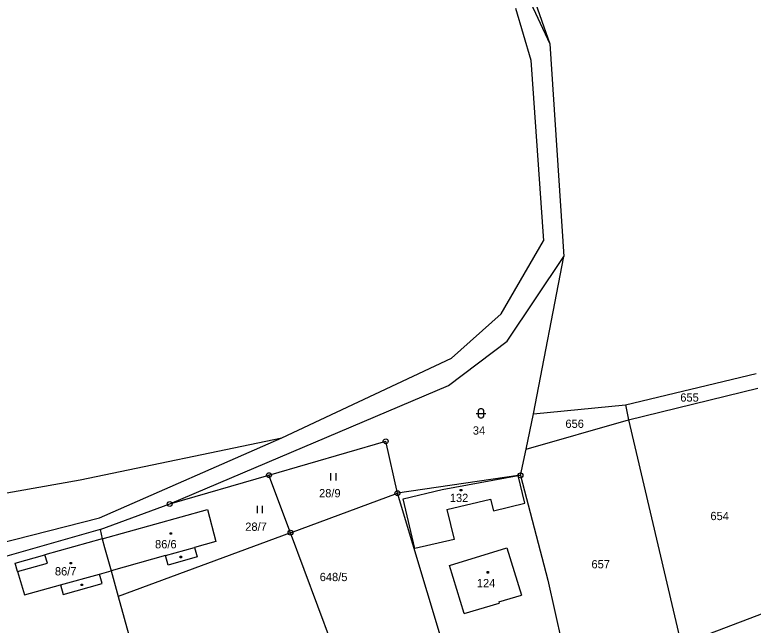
# Model space of a CAD drawing. Extents: x -794142 to -791199, y -1109267 to -1105626.
# Drawn here: x -793464.4 to -793312.7, y -1107558.1 to -1107432.6 of the extents above; entities that cross this region are included whole.
import ezdxf

# ---------------------------------------------------------------- set-up
doc = ezdxf.new("R2010")
doc.units = 0
for name, color, linetype in [('Vrstva 1', 7, 'Continuous'), ('Vrstva 14', 7, 'Continuous'), ('Vrstva 15', 7, 'Continuous'), ('Vrstva 2', 7, 'Continuous'), ('Vrstva 23', 7, 'Continuous'), ('Vrstva 25', 7, 'Continuous'), ('Vrstva 28', 7, 'Continuous')]:
    doc.layers.add(name, color=color, linetype=linetype)

msp = doc.modelspace()

# ---------------------------------------------------------------- linework, layer by layer
at = {"layer": 'Vrstva 1'}
for p, q in [((-793371.44, -1107390.18), (-793354.46, -1107438.54)), ((-793375.72, -1107392.87), (-793354.46, -1107438.54)), ((-793361.55, -1107431.24), (-793358.36, -1107441.93)), ((-793354.46, -1107438.54), (-793351.62, -1107482.26)), ((-793358.36, -1107441.93), (-793355.78, -1107479.02)), ((-793364.52, -1107494.08), (-793355.78, -1107479.02)), ((-793363.27, -1107499.66), (-793351.62, -1107482.26)), ((-793357.81, -1107514.64), (-793351.62, -1107482.26)), ((-793374.67, -1107503.15), (-793364.52, -1107494.08)), ((-793375.33, -1107508.81), (-793363.27, -1107499.66)), ((-793409.53, -1107519.55), (-793374.67, -1107503.15)), ((-793338.94, -1107512.75), (-793312.08, -1107506.35)), ((-793432.59, -1107533.14), (-793375.33, -1107508.81)), ((-793338.31, -1107515.86), (-793311.77, -1107509.33)), ((-793357.81, -1107514.64), (-793338.94, -1107512.75)), ((-793338.94, -1107512.75), (-793338.31, -1107515.86)), ((-793359.37, -1107521.88), (-793357.81, -1107514.64)), ((-793359.37, -1107521.88), (-793338.31, -1107515.86)), ((-793338.31, -1107515.86), (-793327.5, -1107562.01)), ((-793451, -1107528.21), (-793409.53, -1107519.55)), ((-793446.99, -1107536), (-793409.53, -1107519.55)), ((-793412.19, -1107527.22), (-793388.2, -1107520.25)), ((-793385.8, -1107530.91), (-793388.2, -1107520.25)), ((-793360.52, -1107527.26), (-793359.37, -1107521.88)), ((-793432.59, -1107533.14), (-793412.19, -1107527.22)), ((-793407.78, -1107539.04), (-793412.19, -1107527.22)), ((-793360.99, -1107527.28), (-793385.8, -1107530.91)), ((-793376.62, -1107530.18), (-793360.99, -1107527.28)), ((-793360.52, -1107527.26), (-793360.99, -1107527.28)), ((-793359.62, -1107532.97), (-793360.99, -1107527.28)), ((-793360.52, -1107527.26), (-793354.93, -1107548.78)), ((-793504.55, -1107537.5), (-793451, -1107528.21)), ((-793384.61, -1107532.1), (-793376.62, -1107530.18)), ((-793407.78, -1107539.04), (-793385.8, -1107530.91)), ((-793376.27, -1107562.47), (-793385.8, -1107530.91)), ((-793446.9, -1107538.36), (-793432.59, -1107533.14)), ((-793382.2, -1107542.31), (-793384.61, -1107532.1)), ((-793375.67, -1107534.27), (-793366.66, -1107532.13)), ((-793366.66, -1107532.13), (-793366.05, -1107534.58)), ((-793366.05, -1107534.58), (-793359.62, -1107532.97)), ((-793446.44, -1107540.32), (-793424.83, -1107534.3)), ((-793424.83, -1107534.3), (-793423.09, -1107540.85)), ((-793375.67, -1107534.27), (-793374.16, -1107540.45)), ((-793490.03, -1107546.86), (-793446.99, -1107536)), ((-793446.9, -1107538.36), (-793483.13, -1107548.72)), ((-793446.9, -1107538.36), (-793446.44, -1107540.32)), ((-793407.78, -1107539.04), (-793443.16, -1107552.13)), ((-793395.22, -1107572.72), (-793407.78, -1107539.04)), ((-793446.44, -1107540.32), (-793458.22, -1107543.57)), ((-793446.44, -1107540.32), (-793445.96, -1107542.06)), ((-793423.09, -1107540.85), (-793427.47, -1107542.08)), ((-793374.16, -1107540.45), (-793382.2, -1107542.31)), ((-793445.96, -1107542.06), (-793444.61, -1107546.87)), ((-793427.47, -1107542.08), (-793426.93, -1107544.02)), ((-793375.13, -1107545.76), (-793363.29, -1107542.19)), ((-793363.29, -1107542.19), (-793360.33, -1107551.86)), ((-793464.36, -1107545.3), (-793458.22, -1107543.57)), ((-793433.44, -1107543.75), (-793444.61, -1107546.87)), ((-793432.89, -1107545.7), (-793433.44, -1107543.75)), ((-793426.93, -1107544.02), (-793432.89, -1107545.7)), ((-793463.87, -1107547.03), (-793464.36, -1107545.3)), ((-793463.87, -1107547.03), (-793462.45, -1107551.85)), ((-793447.02, -1107547.54), (-793444.61, -1107546.87)), ((-793444.61, -1107546.87), (-793443.16, -1107552.13)), ((-793372.09, -1107555.68), (-793375.13, -1107545.76)), ((-793446.47, -1107549.52), (-793447.02, -1107547.54)), ((-793462.45, -1107551.85), (-793455.01, -1107549.77)), ((-793455.01, -1107549.77), (-793454.46, -1107551.75)), ((-793454.46, -1107551.75), (-793446.47, -1107549.52)), ((-793354.93, -1107548.78), (-793349.5, -1107572.6)), ((-793443.16, -1107552.13), (-793440.7, -1107561.08)), ((-793364.99, -1107553.27), (-793360.33, -1107551.86)), ((-793302.15, -1107552.37), (-793327.5, -1107562.01)), ((-793372.09, -1107555.68), (-793364.91, -1107553.53)), ((-793364.99, -1107553.27), (-793364.91, -1107553.53))]:
    msp.add_line(p, q, dxfattribs=at)
at = {"layer": 'Vrstva 2'}
for p, q in [((-793433.44, -1107543.75), (-793427.47, -1107542.08)), ((-793457.73, -1107545.3), (-793458.22, -1107543.57)), ((-793463.87, -1107547.03), (-793457.73, -1107545.3)), ((-793455.01, -1107549.77), (-793447.02, -1107547.54))]:
    msp.add_line(p, q, dxfattribs=at)
at = {"layer": 'Vrstva 23'}
for p, q in [((-793369.04, -1107513.71), (-793368.94, -1107513.61)), ((-793368.94, -1107513.61), (-793368.74, -1107513.51)), ((-793368.74, -1107513.51), (-793368.54, -1107513.51)), ((-793368.54, -1107513.51), (-793368.34, -1107513.61)), ((-793368.34, -1107513.61), (-793368.24, -1107513.71)), ((-793369.64, -1107514.51), (-793367.64, -1107514.51)), ((-793369.14, -1107513.91), (-793369.04, -1107513.71)), ((-793369.14, -1107515.11), (-793369.14, -1107513.91)), ((-793369.04, -1107515.31), (-793369.14, -1107515.11)), ((-793368.24, -1107513.71), (-793368.14, -1107513.91)), ((-793368.14, -1107515.11), (-793368.24, -1107515.31)), ((-793368.14, -1107513.91), (-793368.14, -1107515.11)), ((-793368.94, -1107515.41), (-793369.04, -1107515.31)), ((-793368.74, -1107515.51), (-793368.94, -1107515.41)), ((-793368.54, -1107515.51), (-793368.74, -1107515.51)), ((-793368.34, -1107515.41), (-793368.54, -1107515.51)), ((-793368.24, -1107515.31), (-793368.34, -1107515.41)), ((-793399.47, -1107528.3), (-793399.47, -1107526.8)), ((-793398.47, -1107526.8), (-793398.47, -1107528.3)), ((-793414.56, -1107535.05), (-793414.56, -1107533.55)), ((-793413.56, -1107533.55), (-793413.56, -1107535.05))]:
    msp.add_line(p, q, dxfattribs=at)
at = {"layer": 'Vrstva 25'}
for p, q in [((-793372.9, -1107530.15), (-793372.6, -1107530.15)), ((-793372.9, -1107530.45), (-793372.9, -1107530.15)), ((-793372.6, -1107530.15), (-793372.6, -1107530.45)), ((-793372.6, -1107530.45), (-793372.9, -1107530.45)), ((-793432.53, -1107539.05), (-793432.23, -1107539.05)), ((-793432.53, -1107539.35), (-793432.53, -1107539.05)), ((-793432.23, -1107539.35), (-793432.53, -1107539.35)), ((-793432.23, -1107539.05), (-793432.23, -1107539.35)), ((-793430.47, -1107543.88), (-793430.17, -1107543.88)), ((-793430.47, -1107544.18), (-793430.47, -1107543.88)), ((-793430.17, -1107543.88), (-793430.17, -1107544.18)), ((-793453.05, -1107545.15), (-793452.75, -1107545.15)), ((-793453.05, -1107545.45), (-793453.05, -1107545.15)), ((-793452.75, -1107545.45), (-793453.05, -1107545.45)), ((-793452.75, -1107545.15), (-793452.75, -1107545.45)), ((-793430.17, -1107544.18), (-793430.47, -1107544.18)), ((-793367.39, -1107547.04), (-793367.09, -1107547.04)), ((-793367.39, -1107547.34), (-793367.39, -1107547.04)), ((-793367.09, -1107547.04), (-793367.09, -1107547.34)), ((-793367.09, -1107547.34), (-793367.39, -1107547.34)), ((-793450.79, -1107549.61), (-793450.49, -1107549.61)), ((-793450.79, -1107549.91), (-793450.79, -1107549.61)), ((-793450.49, -1107549.91), (-793450.79, -1107549.91)), ((-793450.49, -1107549.61), (-793450.49, -1107549.91))]:
    msp.add_line(p, q, dxfattribs=at)
at = {"layer": 'Vrstva 28'}
for centre, radius in [((-793388.2, -1107520.25), 0.5), ((-793388.2, -1107520.25), 0.01), ((-793412.19, -1107527.22), 0.5), ((-793412.19, -1107527.22), 0.01), ((-793360.52, -1107527.26), 0.5), ((-793360.52, -1107527.26), 0.01), ((-793385.8, -1107530.91), 0.5), ((-793385.8, -1107530.91), 0.01), ((-793432.59, -1107533.14), 0.5), ((-793432.59, -1107533.14), 0.01), ((-793407.78, -1107539.04), 0.5), ((-793407.78, -1107539.04), 0.01)]:
    msp.add_circle(centre, radius, dxfattribs=at)

# ---------------------------------------------------------------- texts
at = {"layer": 'Vrstva 14'}
for s, p in [('655', (-793327.679, -1107512.1)), ('656', (-793351.283, -1107517.5)), ('34', (-793370.303, -1107518.88)), ('28/9', (-793401.9, -1107531.77)), ('654', (-793321.489, -1107536.46)), ('28/7', (-793417.066, -1107538.66)), ('657', (-793345.93, -1107546.37)), ('648/5', (-793401.762, -1107549))]:
    msp.add_text(s, height=1.7, dxfattribs=at).set_placement(p)
at = {"layer": 'Vrstva 15'}
for s, p in [('132', (-793375.04, -1107532.74)), ('86/6', (-793435.6, -1107542.26)), ('86/7', (-793456.176, -1107547.83)), ('124', (-793369.476, -1107550.26))]:
    msp.add_text(s, height=1.7, dxfattribs=at).set_placement(p)

doc.saveas('drawing.dxf')
